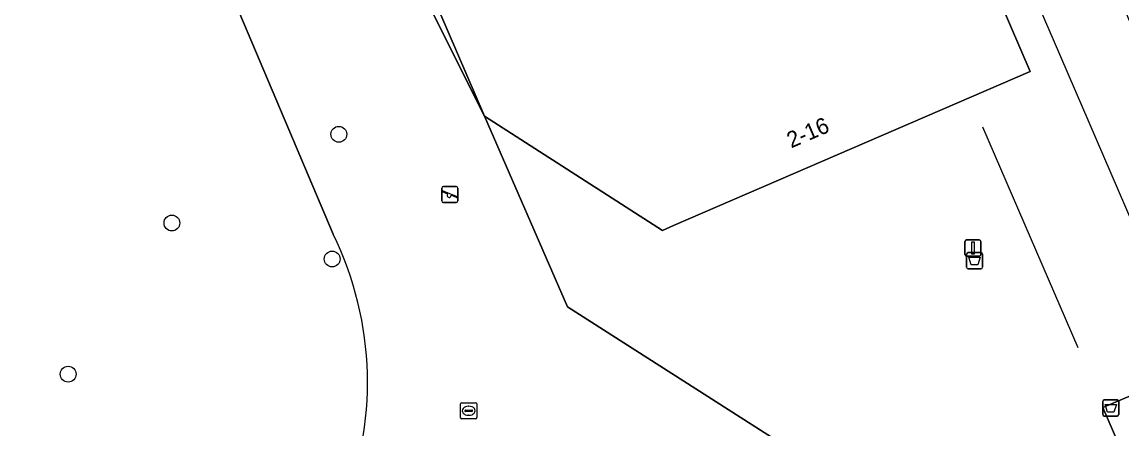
# Model space of a CAD drawing. Extents: x 155640 to 156811, y 382821 to 384049.
# Drawn here: x 156623.8 to 156691.9, y 383667.4 to 383692.6 of the extents above; entities that cross this region are included whole.
import ezdxf

# ---------------------------------------------------------------- set-up
doc = ezdxf.new("R2010")
doc.units = 0
for name, color, linetype in [('IMGEO_Afvalbak', 7, 'Continuous'), ('IMGEO_Boom', 7, 'Continuous'), ('IMGEO_Erf', 7, 'Continuous'), ('IMGEO_Groenvoorziening', 7, 'Continuous'), ('IMGEO_Lichtmast', 7, 'Continuous'), ('IMGEO_Lijnafwatering', 7, 'Continuous'), ('IMGEO_Pand', 7, 'Continuous'), ('IMGEO_Pand_nummerreeks', 7, 'Continuous'), ('IMGEO_Pand_overbouw', 7, 'Continuous'), ('IMGEO_Rioolput', 7, 'Continuous'), ('IMGEO_Speelvoorziening', 7, 'Continuous'), ('IMGEO_Terreindeel_zand', 7, 'Continuous'), ('IMGEO_Voetpad_open', 7, 'Continuous')]:
    doc.layers.add(name, color=color, linetype=linetype)

msp = doc.modelspace()

# ---------------------------------------------------------------- linework, layer by layer
at = {"layer": 'IMGEO_Afvalbak'}
for p, q in [((156682.282, 383677.406), (156682.282, 383678.206)), ((156682.282, 383678.206), (156682.282, 383677.406)), ((156682.382, 383678.306), (156683.172, 383678.306)), ((156683.172, 383678.306), (156682.382, 383678.306)), ((156683.272, 383678.206), (156683.272, 383677.406)), ((156683.272, 383677.406), (156683.272, 383678.206)), ((156683.172, 383677.306), (156682.382, 383677.306)), ((156682.382, 383677.306), (156683.172, 383677.306)), ((156690.815, 383669.195), (156691.605, 383669.195)), ((156691.605, 383669.195), (156690.815, 383669.195)), ((156690.715, 383668.295), (156690.715, 383669.095)), ((156690.715, 383669.095), (156690.715, 383668.295)), ((156691.705, 383669.095), (156691.705, 383668.295)), ((156691.705, 383668.295), (156691.705, 383669.095)), ((156691.605, 383668.195), (156690.815, 383668.195)), ((156690.815, 383668.195), (156691.605, 383668.195))]:
    msp.add_line(p, q, dxfattribs=at)
for points in [[(156682.425, 383678.02), (156683.129, 383678.02), (156682.98, 383677.55), (156682.574, 383677.55), (156682.425, 383678.02)], [(156690.858, 383668.909), (156691.562, 383668.909), (156691.413, 383668.439), (156691.007, 383668.439), (156690.858, 383668.909)]]:
    msp.add_lwpolyline(points, dxfattribs=at)
for centre, start, end in [((156682.382, 383678.206), 90, 180), ((156682.382, 383678.206), 90, 180), ((156683.172, 383678.206), 0, 90), ((156683.172, 383678.206), 360, 90), ((156682.382, 383677.406), 180, 270), ((156682.382, 383677.406), 180, 270), ((156683.172, 383677.406), 270, 0), ((156683.172, 383677.406), 270, 0), ((156690.815, 383669.095), 90, 180), ((156690.815, 383669.095), 90, 180), ((156691.605, 383669.095), 0, 90), ((156691.605, 383669.095), 360, 90), ((156690.815, 383668.295), 180, 270), ((156690.815, 383668.295), 180, 270), ((156691.605, 383668.295), 270, 0), ((156691.605, 383668.295), 270, 0)]:
    msp.add_arc(centre, 0.1, start, end, dxfattribs=at)
at = {"layer": 'IMGEO_Boom'}
for centre in [(156643.384, 383685.631), (156633.039, 383680.136), (156642.97, 383677.91), (156626.609, 383670.786)]:
    msp.add_circle(centre, 0.489, dxfattribs=at)
at = {"layer": 'IMGEO_Erf'}
msp.add_lwpolyline([(156685.113, 383709.502), (156678.78, 383706.772), (156686.219, 383689.506), (156664.119, 383679.976), (156663.435, 383679.681), (156652.408, 383686.743), (156657.547, 383674.961), (156681.918, 383659.404), (156689.34, 383662.687), (156692.704, 383664.144), (156690.725, 383668.733), (156700.865, 383673.021)], close=True, dxfattribs=at)
at = {"layer": 'IMGEO_Groenvoorziening'}
for points in [[(156690.826, 383654.358), (156690.3, 383654.11), (156681.918, 383659.404), (156657.547, 383674.961), (156652.408, 383686.743), (156632.481, 383726.499)], [(156643.03, 383679.444), (156630.667, 383708.624), (156627.069, 383717.269)], [(156627.069, 383717.269), (156630.667, 383708.624), (156643.03, 383679.444)]]:
    msp.add_lwpolyline(points, dxfattribs=at)
msp.add_arc((156624.43, 383670.29), 20.73, 336.77723, 26.20459, dxfattribs=at)
msp.add_arc((156624.43, 383670.29), 20.73, 336.77723, 26.20459, dxfattribs=at)
at = {"layer": 'IMGEO_Lichtmast'}
for p, q in [((156682.178, 383678.196), (156682.178, 383678.996)), ((156682.178, 383678.996), (156682.178, 383678.196)), ((156682.278, 383679.096), (156683.068, 383679.096)), ((156683.068, 383679.096), (156682.278, 383679.096)), ((156683.168, 383678.996), (156683.168, 383678.196)), ((156683.168, 383678.196), (156683.168, 383678.996)), ((156683.068, 383678.096), (156682.278, 383678.096)), ((156682.278, 383678.096), (156683.068, 383678.096))]:
    msp.add_line(p, q, dxfattribs=at)
msp.add_lwpolyline([(156682.598, 383678.971), (156682.748, 383678.971), (156682.748, 383678.221), (156682.598, 383678.221), (156682.598, 383678.971)], dxfattribs=at)
for centre, start, end in [((156682.278, 383678.996), 90, 180), ((156682.278, 383678.996), 90, 180), ((156683.068, 383678.996), 0, 90), ((156683.068, 383678.996), 360, 90), ((156682.278, 383678.196), 180, 270), ((156682.278, 383678.196), 180, 270), ((156683.068, 383678.196), 270, 0), ((156683.068, 383678.196), 270, 0)]:
    msp.add_arc(centre, 0.1, start, end, dxfattribs=at)
at = {"layer": 'IMGEO_Lijnafwatering'}
for points in [[(156680.485, 383708.012), (156687.636, 383691.485)], [(156687.636, 383691.485), (156694.786, 383674.957)], [(156683.257, 383686.1), (156689.182, 383672.428)]]:
    msp.add_lwpolyline(points, dxfattribs=at)
at = {"layer": 'IMGEO_Pand'}
msp.add_lwpolyline([(156664.288, 383740.247), (156653.167, 383765.904), (156623.751, 383753.224), (156634.828, 383727.527), (156638.38, 383719.285), (156637.28, 383718.81), (156639.074, 383714.661), (156640.18, 383715.109), (156652.408, 383686.743), (156663.435, 383679.681), (156664.119, 383679.976), (156686.219, 383689.506), (156678.78, 383706.772), (156675.581, 383714.191)], close=True, dxfattribs=at)
at = {"layer": 'IMGEO_Pand_overbouw'}
msp.add_lwpolyline([(156634.828, 383727.527), (156632.481, 383726.499), (156652.408, 383686.743), (156640.18, 383715.109), (156639.074, 383714.661), (156637.28, 383718.81), (156638.38, 383719.285)], close=True, dxfattribs=at)
at = {"layer": 'IMGEO_Rioolput'}
for p, q in [((156650.929, 383668.097), (156650.929, 383668.949)), ((156651.004, 383669.023), (156651.856, 383669.023)), ((156651.188, 383668.517), (156651.188, 383668.529)), ((156651.626, 383668.48), (156651.228, 383668.48)), ((156651.231, 383668.566), (156651.629, 383668.566)), ((156651.417, 383668.803), (156651.442, 383668.803)), ((156651.672, 383668.529), (156651.672, 383668.517)), ((156651.93, 383668.949), (156651.93, 383668.097)), ((156651.856, 383668.023), (156651.004, 383668.023)), ((156651.44, 383668.243), (156651.415, 383668.243))]:
    msp.add_line(p, q, dxfattribs=at)
for points in [[(156650.929, 383668.097), (156650.929, 383668.949)], [(156651.004, 383669.023), (156651.856, 383669.023)], [(156651.93, 383668.949), (156651.93, 383668.097)], [(156651.856, 383668.023), (156651.004, 383668.023)]]:
    msp.add_lwpolyline(points, dxfattribs=at)
for centre, radius, start, end in [((156651.006, 383668.947), 0.0765, 91.55205, 178.44795), ((156651.006, 383668.947), 0.0765, 91.55205, 178.44795), ((156651.228, 383668.526), 0.0403, 85.87752, 175.75265), ((156651.225, 383668.516), 0.0366, 178.93798, 274.71019), ((156651.629, 383668.523), 0.043, 264.86636, 352.45326), ((156651.633, 383668.528), 0.0386, 1.73085, 96.63898), ((156651.854, 383668.947), 0.0765, 1.55205, 88.44795), ((156651.854, 383668.947), 0.0765, 1.55205, 88.44795), ((156651.006, 383668.099), 0.0765, 181.55205, 268.44795), ((156651.006, 383668.099), 0.0765, 181.55205, 268.44795), ((156651.854, 383668.099), 0.0765, 271.55205, 358.44795), ((156651.854, 383668.099), 0.0765, 271.55205, 358.44795)]:
    msp.add_arc(centre, radius, start, end, dxfattribs=at)
for centre, major_axis, ratio, start_param, end_param in [((156651.416, 383668.523), (-0.387, 0.002), 0.722429, 4.712389, 7.853982), ((156651.441, 383668.523), (-0.39, 0.002), 0.717154, 1.570796, 4.712389)]:
    msp.add_ellipse(centre, major_axis=major_axis, ratio=ratio, start_param=start_param, end_param=end_param, dxfattribs=at)
at = {"layer": 'IMGEO_Speelvoorziening'}
for p, q in [((156649.761, 383681.504), (156649.761, 383682.304)), ((156649.761, 383682.304), (156649.761, 383681.504)), ((156649.83, 383682.129), (156650.706, 383681.776)), ((156649.861, 383682.404), (156650.651, 383682.404)), ((156650.651, 383682.404), (156649.861, 383682.404)), ((156650.751, 383682.304), (156650.751, 383681.504)), ((156650.751, 383681.504), (156650.751, 383682.304)), ((156650.144, 383681.932), (156649.805, 383682.069)), ((156650.682, 383681.716), (156650.342, 383681.853)), ((156650.651, 383681.404), (156649.861, 383681.404)), ((156649.861, 383681.404), (156650.651, 383681.404))]:
    msp.add_line(p, q, dxfattribs=at)
for centre, radius, start, end in [((156649.861, 383682.304), 0.1, 90, 180), ((156649.861, 383682.304), 0.1, 90, 180), ((156649.818, 383682.099), 0.0327, 68.07798, 248.07798), ((156650.651, 383682.304), 0.1, 0, 90), ((156650.651, 383682.304), 0.1, 360, 90), ((156649.861, 383681.504), 0.1, 180, 270), ((156649.861, 383681.504), 0.1, 180, 270), ((156650.223, 383681.842), 0.12, 130.99278, 5.16318), ((156650.651, 383681.504), 0.1, 270, 0), ((156650.651, 383681.504), 0.1, 270, 0), ((156650.694, 383681.746), 0.0327, 248.07798, 68.07798)]:
    msp.add_arc(centre, radius, start, end, dxfattribs=at)
at = {"layer": 'IMGEO_Terreindeel_zand'}
msp.add_lwpolyline([(156702.778, 383668.591), (156700.865, 383673.021), (156690.725, 383668.733), (156692.704, 383664.144)], close=True, dxfattribs=at)
at = {"layer": 'IMGEO_Voetpad_open'}
msp.add_lwpolyline([(156640.18, 383715.109), (156639.074, 383714.661), (156637.28, 383718.81), (156638.38, 383719.285), (156634.828, 383727.527), (156632.481, 383726.499), (156652.408, 383686.743)], close=True, dxfattribs=at)

# ---------------------------------------------------------------- texts
at = {"layer": 'IMGEO_Pand_nummerreeks'}
msp.add_text('2-16', height=1, rotation=23.32511, dxfattribs=at).set_placement((156671.409, 383684.753))

doc.saveas('drawing.dxf')
